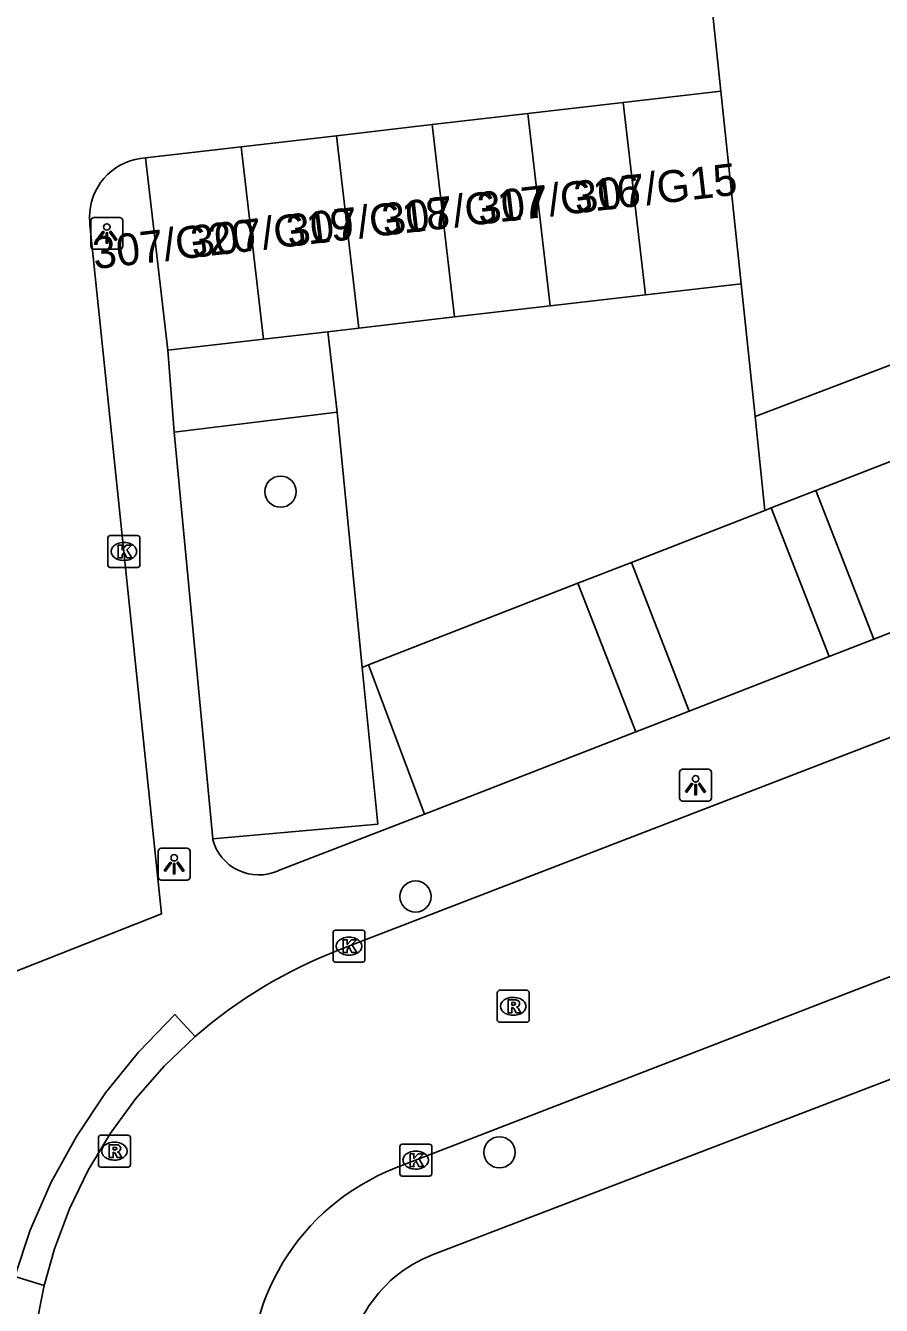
# Model space of a CAD drawing. Extents: x 161253 to 161848, y 384872 to 385383.
# Drawn here: x 161319.1 to 161345.9, y 385275.83 to 385315.91 of the extents above; entities that cross this region are included whole.
import ezdxf

# ---------------------------------------------------------------- set-up
doc = ezdxf.new("R2010")
doc.units = 0
for name, color, linetype in [('IMGEO_Boom', 7, 'Continuous'), ('IMGEO_Groenvoorziening', 7, 'Continuous'), ('IMGEO_Kolk', 7, 'Continuous'), ('IMGEO_Lichtpunt', 7, 'Continuous'), ('IMGEO_Pand', 7, 'Continuous'), ('IMGEO_Pand_nummerreeks', 7, 'Continuous'), ('IMGEO_Parkeervlak_open', 7, 'Continuous'), ('IMGEO_Rijbaan_lokaal_open', 7, 'Continuous'), ('IMGEO_Rioolput', 7, 'Continuous'), ('IMGEO_Voetpad_open', 7, 'Continuous')]:
    doc.layers.add(name, color=color, linetype=linetype)

msp = doc.modelspace()

# ---------------------------------------------------------------- linework, layer by layer
at = {"layer": 'IMGEO_Boom'}
for centre in [(161327.085, 385301.316), (161331.313, 385288.635), (161333.94, 385280.622)]:
    msp.add_circle(centre, 0.489, dxfattribs=at)
at = {"layer": 'IMGEO_Groenvoorziening'}
msp.add_lwpolyline([(161342.253, 385300.73), (161341.943, 385303.675)], dxfattribs=at)
at = {"layer": 'IMGEO_Kolk'}
for p, q in [((161321.677, 385299.017), (161321.677, 385299.869)), ((161321.752, 385299.943), (161322.604, 385299.943)), ((161322.678, 385299.869), (161322.678, 385299.017)), ((161322.165, 385299.723), (161322.19, 385299.723)), ((161322.188, 385299.163), (161322.163, 385299.163)), ((161322.604, 385298.943), (161321.752, 385298.943)), ((161328.727, 385286.654), (161328.727, 385287.506)), ((161328.802, 385287.58), (161329.654, 385287.58)), ((161329.215, 385287.36), (161329.24, 385287.36)), ((161329.728, 385287.506), (161329.728, 385286.654)), ((161329.654, 385286.58), (161328.802, 385286.58)), ((161329.238, 385286.8), (161329.213, 385286.8)), ((161330.818, 385279.952), (161330.818, 385280.804)), ((161330.893, 385280.878), (161331.745, 385280.878)), ((161331.306, 385280.658), (161331.331, 385280.658)), ((161331.819, 385280.804), (161331.819, 385279.952)), ((161331.745, 385279.878), (161330.893, 385279.878)), ((161331.329, 385280.098), (161331.304, 385280.098))]:
    msp.add_line(p, q, dxfattribs=at)
for points in [[(161321.677, 385299.017), (161321.677, 385299.869)], [(161321.752, 385299.943), (161322.604, 385299.943)], [(161322.678, 385299.869), (161322.678, 385299.017)], [(161321.998, 385299.643), (161322.121, 385299.643), (161322.121, 385299.492), (161322.251, 385299.643), (161322.415, 385299.643), (161322.269, 385299.492), (161322.422, 385299.243), (161322.27, 385299.243), (161322.185, 385299.407), (161322.121, 385299.34), (161322.121, 385299.243), (161321.998, 385299.243), (161321.998, 385299.643)], [(161322.604, 385298.943), (161321.752, 385298.943)], [(161328.727, 385286.654), (161328.727, 385287.506)], [(161328.802, 385287.58), (161329.654, 385287.58)], [(161329.728, 385287.506), (161329.728, 385286.654)], [(161329.048, 385287.28), (161329.171, 385287.28), (161329.171, 385287.129), (161329.301, 385287.28), (161329.465, 385287.28), (161329.319, 385287.129), (161329.472, 385286.88), (161329.32, 385286.88), (161329.235, 385287.044), (161329.171, 385286.977), (161329.171, 385286.88), (161329.048, 385286.88), (161329.048, 385287.28)], [(161329.654, 385286.58), (161328.802, 385286.58)], [(161330.818, 385279.952), (161330.818, 385280.804)], [(161330.893, 385280.878), (161331.745, 385280.878)], [(161331.139, 385280.578), (161331.262, 385280.578), (161331.262, 385280.427), (161331.392, 385280.578), (161331.556, 385280.578), (161331.41, 385280.427), (161331.563, 385280.178), (161331.411, 385280.178), (161331.326, 385280.342), (161331.262, 385280.275), (161331.262, 385280.178), (161331.139, 385280.178), (161331.139, 385280.578)], [(161331.819, 385280.804), (161331.819, 385279.952)], [(161331.745, 385279.878), (161330.893, 385279.878)]]:
    msp.add_lwpolyline(points, dxfattribs=at)
for centre, start, end in [((161321.754, 385299.867), 91.552, 178.448), ((161321.754, 385299.867), 91.552, 178.448), ((161322.602, 385299.867), 1.552, 88.448), ((161322.602, 385299.867), 1.552, 88.448), ((161321.754, 385299.019), 181.552, 268.448), ((161321.754, 385299.019), 181.552, 268.448), ((161322.602, 385299.019), 271.552, 358.448), ((161322.602, 385299.019), 271.552, 358.448), ((161328.804, 385287.504), 91.552, 178.448), ((161328.804, 385287.504), 91.552, 178.448), ((161329.652, 385287.504), 1.552, 88.448), ((161329.652, 385287.504), 1.552, 88.448), ((161328.804, 385286.656), 181.552, 268.448), ((161328.804, 385286.656), 181.552, 268.448), ((161329.652, 385286.656), 271.552, 358.448), ((161329.652, 385286.656), 271.552, 358.448), ((161330.895, 385280.802), 91.552, 178.448), ((161330.895, 385280.802), 91.552, 178.448), ((161331.743, 385280.802), 1.552, 88.448), ((161331.743, 385280.802), 1.552, 88.448), ((161330.895, 385279.954), 181.552, 268.448), ((161330.895, 385279.954), 181.552, 268.448), ((161331.743, 385279.954), 271.552, 358.448), ((161331.743, 385279.954), 271.552, 358.448)]:
    msp.add_arc(centre, 0.0765, start, end, dxfattribs=at)
for centre, major_axis, ratio, start_param, end_param in [((161322.164, 385299.443), (-0.387, 0.002), 0.722429, 4.712389, 7.853982), ((161322.189, 385299.443), (-0.39, 0.002), 0.717154, 1.570796, 4.712389), ((161329.214, 385287.08), (-0.387, 0.002), 0.722429, 4.712389, 7.853982), ((161329.239, 385287.08), (-0.39, 0.002), 0.717154, 1.570796, 4.712389), ((161331.305, 385280.378), (-0.387, 0.002), 0.722429, 4.712389, 7.853982), ((161331.33, 385280.378), (-0.39, 0.002), 0.717154, 1.570796, 4.712389)]:
    msp.add_ellipse(centre, major_axis=major_axis, ratio=ratio, start_param=start_param, end_param=end_param, dxfattribs=at)
at = {"layer": 'IMGEO_Lichtpunt'}
for p, q in [((161321.144, 385309.808), (161321.144, 385309.001)), ((161321.144, 385309.808), (161321.144, 385309.001)), ((161322.046, 385309.903), (161321.238, 385309.903)), ((161322.046, 385309.903), (161321.238, 385309.903)), ((161322.14, 385309.001), (161322.14, 385309.808)), ((161322.14, 385309.001), (161322.14, 385309.808)), ((161321.238, 385308.907), (161322.046, 385308.907)), ((161321.238, 385308.907), (161322.046, 385308.907)), ((161340.485, 385292.62), (161339.677, 385292.62)), ((161340.485, 385292.62), (161339.677, 385292.62)), ((161339.583, 385292.525), (161339.583, 385291.718)), ((161339.583, 385292.525), (161339.583, 385291.718)), ((161340.579, 385291.718), (161340.579, 385292.525)), ((161340.579, 385291.718), (161340.579, 385292.525)), ((161339.677, 385291.624), (161340.485, 385291.624)), ((161339.677, 385291.624), (161340.485, 385291.624)), ((161323.254, 385290.051), (161323.254, 385289.244)), ((161323.254, 385290.051), (161323.254, 385289.244)), ((161324.156, 385290.146), (161323.348, 385290.146)), ((161324.156, 385290.146), (161323.348, 385290.146)), ((161324.25, 385289.244), (161324.25, 385290.051)), ((161324.25, 385289.244), (161324.25, 385290.051)), ((161323.348, 385289.15), (161324.156, 385289.15)), ((161323.348, 385289.15), (161324.156, 385289.15))]:
    msp.add_line(p, q, dxfattribs=at)
for points in [[(161321.518, 385309.472), (161321.557, 385309.444), (161321.369, 385309.182), (161321.331, 385309.209), (161321.518, 385309.472)], [(161321.62, 385309.424), (161321.667, 385309.424), (161321.667, 385309.102), (161321.62, 385309.102), (161321.62, 385309.424)], [(161321.73, 385309.444), (161321.768, 385309.471), (161321.955, 385309.209), (161321.916, 385309.181), (161321.73, 385309.444)], [(161339.957, 385292.189), (161339.996, 385292.161), (161339.808, 385291.899), (161339.77, 385291.926), (161339.957, 385292.189)], [(161340.169, 385292.161), (161340.207, 385292.188), (161340.394, 385291.926), (161340.355, 385291.898), (161340.169, 385292.161)], [(161340.059, 385292.141), (161340.106, 385292.141), (161340.106, 385291.819), (161340.059, 385291.819), (161340.059, 385292.141)], [(161323.628, 385289.715), (161323.667, 385289.687), (161323.479, 385289.425), (161323.441, 385289.452), (161323.628, 385289.715)], [(161323.73, 385289.667), (161323.777, 385289.667), (161323.777, 385289.345), (161323.73, 385289.345), (161323.73, 385289.667)], [(161323.84, 385289.687), (161323.878, 385289.714), (161324.065, 385289.452), (161324.026, 385289.424), (161323.84, 385289.687)]]:
    msp.add_lwpolyline(points, dxfattribs=at)
for centre in [(161321.643, 385309.606), (161340.082, 385292.323), (161323.753, 385289.849)]:
    msp.add_circle(centre, 0.0994, dxfattribs=at)
for centre, start, end in [((161321.238, 385309.808), 90, 180), ((161321.238, 385309.808), 90, 180), ((161322.046, 385309.808), 0, 90), ((161322.046, 385309.808), 0, 90), ((161321.238, 385309.001), 180, 270), ((161321.238, 385309.001), 180, 270), ((161322.046, 385309.001), 270, 0), ((161322.046, 385309.001), 270, 360), ((161339.677, 385292.525), 90, 180), ((161339.677, 385292.525), 90, 180), ((161340.485, 385292.525), 0, 90), ((161340.485, 385292.525), 0, 90), ((161339.677, 385291.718), 180, 270), ((161339.677, 385291.718), 180, 270), ((161340.485, 385291.718), 270, 0), ((161340.485, 385291.718), 270, 360), ((161323.348, 385290.051), 90, 180), ((161323.348, 385290.051), 90, 180), ((161324.156, 385290.051), 0, 90), ((161324.156, 385290.051), 0, 90), ((161323.348, 385289.244), 180, 270), ((161323.348, 385289.244), 180, 270), ((161324.156, 385289.244), 270, 0), ((161324.156, 385289.244), 270, 360)]:
    msp.add_arc(centre, 0.0946, start, end, dxfattribs=at)
at = {"layer": 'IMGEO_Pand'}
for points in [[(161340.871, 385313.86), (161339.824, 385323.814)], [(161340.871, 385313.86), (161337.816, 385313.505)], [(161341.506, 385307.829), (161340.871, 385313.86)], [(161334.824, 385313.158), (161337.816, 385313.505)], [(161337.816, 385313.505), (161338.515, 385307.482)], [(161331.833, 385312.811), (161334.824, 385313.158)], [(161334.824, 385313.158), (161335.523, 385307.135)], [(161328.841, 385312.464), (161331.833, 385312.811)], [(161331.833, 385312.811), (161332.532, 385306.788)], [(161325.85, 385312.117), (161328.841, 385312.464)], [(161328.841, 385312.464), (161329.54, 385306.441)], [(161325.85, 385312.117), (161322.859, 385311.77)], [(161326.548, 385306.094), (161325.85, 385312.117)], [(161322.859, 385311.77), (161323.557, 385305.747)], [(161359.136, 385309.338), (161359.113, 385309.131), (161357.21, 385308.445), (161357.263, 385308.334), (161353.721, 385306.981), (161353.329, 385308.005), (161341.943, 385303.675)], [(161338.515, 385307.482), (161341.506, 385307.829)], [(161341.943, 385303.675), (161341.506, 385307.829)], [(161338.515, 385307.482), (161335.523, 385307.135)], [(161335.523, 385307.135), (161332.532, 385306.788)], [(161332.532, 385306.788), (161329.54, 385306.441)], [(161328.561, 385306.327), (161326.548, 385306.094)], [(161329.54, 385306.441), (161328.561, 385306.327)], [(161323.557, 385305.747), (161326.548, 385306.094)]]:
    msp.add_lwpolyline(points, dxfattribs=at)
at = {"layer": 'IMGEO_Parkeervlak_open'}
for points in [[(161343.848, 385301.35), (161352.373, 385304.672)], [(161328.853, 385303.808), (161329.644, 385295.807)], [(161342.253, 385300.73), (161338.07, 385299.1)], [(161342.45, 385300.807), (161342.253, 385300.73)], [(161336.393, 385298.447), (161329.842, 385295.895)]]:
    msp.add_lwpolyline(points, dxfattribs=at)
at = {"layer": 'IMGEO_Rijbaan_lokaal_open'}
for points in [[(161322.859, 385311.77), (161322.693, 385311.754), (161322.53, 385311.722), (161322.37, 385311.677), (161322.215, 385311.617), (161322.065, 385311.543), (161321.923, 385311.457), (161321.789, 385311.358), (161321.665, 385311.248), (161321.551, 385311.127), (161321.448, 385310.996), (161321.357, 385310.856), (161321.279, 385310.709), (161321.215, 385310.556), (161321.164, 385310.397), (161321.128, 385310.235), (161321.106, 385310.07), (161321.1, 385309.904), (161321.108, 385309.737), (161321.115, 385309.674), (161323.36, 385288.088), (161317.793, 385285.896)], [(161328.923, 385286.962), (161374.2, 385304.421), (161379.805, 385306.58), (161385.091, 385308.618)], [(161356.419, 385290.084), (161330.668, 385280.124)], [(161319.678, 385276.452), (161319.999, 385277.598), (161320.475, 385278.856), (161321.063, 385280.067), (161321.756, 385281.221), (161322.549, 385282.308), (161323.437, 385283.32), (161324.411, 385284.249)], [(161327.141, 385199.049), (161326.822, 385201.971), (161321.575, 385250), (161319.33, 385271.321), (161319.259, 385272.292), (161319.265, 385273.638), (161319.391, 385274.978), (161319.678, 385276.452)]]:
    msp.add_lwpolyline(points, dxfattribs=at)
for centre, radius, start, end in [((161334.322, 385272.875), 15.087, 110.9691, 131.0667), ((161333.288, 385273.455), 7.166, 111.4479, 186.0931)]:
    msp.add_arc(centre, radius, start, end, dxfattribs=at)
at = {"layer": 'IMGEO_Rioolput'}
for p, q in [((161333.871, 385284.771), (161333.871, 385285.623)), ((161333.946, 385285.697), (161334.798, 385285.697)), ((161334.359, 385285.477), (161334.384, 385285.477)), ((161334.872, 385285.623), (161334.872, 385284.771)), ((161334.798, 385284.697), (161333.946, 385284.697)), ((161334.382, 385284.917), (161334.357, 385284.917)), ((161321.38, 385280.234), (161321.38, 385281.086)), ((161321.455, 385281.16), (161322.307, 385281.16)), ((161321.868, 385280.94), (161321.893, 385280.94)), ((161322.381, 385281.086), (161322.381, 385280.234)), ((161322.307, 385280.16), (161321.455, 385280.16)), ((161321.891, 385280.38), (161321.866, 385280.38))]:
    msp.add_line(p, q, dxfattribs=at)
for points in [[(161333.871, 385284.771), (161333.871, 385285.623)], [(161333.946, 385285.697), (161334.798, 385285.697)], [(161334.46, 385285.395), (161334.208, 385285.397), (161334.208, 385284.997)], [(161334.872, 385285.623), (161334.872, 385284.771)], [(161334.208, 385284.997), (161334.332, 385284.997), (161334.332, 385285.159), (161334.343, 385285.159)], [(161334.386, 385285.316), (161334.332, 385285.316), (161334.332, 385285.235)], [(161334.332, 385285.235), (161334.384, 385285.235)], [(161334.39, 385285.13), (161334.461, 385284.997), (161334.601, 385284.997), (161334.536, 385285.123)], [(161334.798, 385284.697), (161333.946, 385284.697)], [(161321.38, 385280.234), (161321.38, 385281.086)], [(161321.455, 385281.16), (161322.307, 385281.16)], [(161322.381, 385281.086), (161322.381, 385280.234)], [(161321.969, 385280.858), (161321.717, 385280.86), (161321.717, 385280.46)], [(161321.717, 385280.46), (161321.841, 385280.46), (161321.841, 385280.622), (161321.852, 385280.622)], [(161321.895, 385280.779), (161321.841, 385280.779), (161321.841, 385280.698)], [(161321.841, 385280.698), (161321.893, 385280.698)], [(161321.899, 385280.593), (161321.97, 385280.46), (161322.11, 385280.46), (161322.045, 385280.586)], [(161322.307, 385280.16), (161321.455, 385280.16)]]:
    msp.add_lwpolyline(points, dxfattribs=at)
for centre, radius, start, end in [((161333.948, 385285.621), 0.0765, 91.552, 178.448), ((161333.948, 385285.621), 0.0765, 91.552, 178.448), ((161334.459, 385285.285), 0.109, 350.3612, 89.416), ((161334.796, 385285.621), 0.0765, 1.552, 88.448), ((161334.796, 385285.621), 0.0765, 1.552, 88.448), ((161334.342, 385285.106), 0.0533, 26.0293, 88.6989), ((161334.368, 385285.424), 0.19, 274.7715, 282.9687), ((161334.392, 385285.22), 0.0964, 77.0061, 93.1865), ((161334.406, 385285.277), 0.0378, 276.6634, 79.6772), ((161334.457, 385285.285), 0.112, 277.5842, 350.9817), ((161334.441, 385285.07), 0.108, 29.5134, 73.7905), ((161333.948, 385284.773), 0.0765, 181.552, 268.448), ((161333.948, 385284.773), 0.0765, 181.552, 268.448), ((161334.796, 385284.773), 0.0765, 271.552, 358.448), ((161334.796, 385284.773), 0.0765, 271.552, 358.448), ((161321.457, 385281.084), 0.0765, 91.552, 178.448), ((161321.457, 385281.084), 0.0765, 91.552, 178.448), ((161322.305, 385281.084), 0.0765, 1.552, 88.448), ((161322.305, 385281.084), 0.0765, 1.552, 88.448), ((161321.851, 385280.569), 0.0533, 26.0293, 88.6989), ((161321.877, 385280.887), 0.19, 274.7715, 282.9687), ((161321.901, 385280.683), 0.0964, 77.0061, 93.1865), ((161321.915, 385280.74), 0.0378, 276.6634, 79.6772), ((161321.968, 385280.748), 0.109, 350.3612, 89.416), ((161321.966, 385280.748), 0.112, 277.5842, 350.9817), ((161321.95, 385280.533), 0.108, 29.5134, 73.7905), ((161321.457, 385280.236), 0.0765, 181.552, 268.448), ((161321.457, 385280.236), 0.0765, 181.552, 268.448), ((161322.305, 385280.236), 0.0765, 271.552, 358.448), ((161322.305, 385280.236), 0.0765, 271.552, 358.448)]:
    msp.add_arc(centre, radius, start, end, dxfattribs=at)
for centre, major_axis, ratio, start_param, end_param in [((161334.358, 385285.197), (-0.387, 0.002), 0.722429, 4.712389, 7.853982), ((161334.383, 385285.197), (-0.39, 0.002), 0.717154, 1.570796, 4.712389), ((161321.867, 385280.66), (-0.387, 0.002), 0.722429, 4.712389, 7.853982), ((161321.892, 385280.66), (-0.39, 0.002), 0.717154, 1.570796, 4.712389)]:
    msp.add_ellipse(centre, major_axis=major_axis, ratio=ratio, start_param=start_param, end_param=end_param, dxfattribs=at)
at = {"layer": 'IMGEO_Voetpad_open'}
for points in [[(161328.561, 385306.327), (161328.853, 385303.808)], [(161323.752, 385303.182), (161323.557, 385305.747)], [(161323.752, 385303.182), (161328.853, 385303.808)], [(161324.958, 385290.439), (161323.752, 385303.182)], [(161343.848, 385301.35), (161342.45, 385300.807)], [(161345.661, 385296.695), (161343.848, 385301.35)], [(161342.45, 385300.807), (161344.263, 385296.151)], [(161354.187, 385300.016), (161345.661, 385296.695)], [(161336.393, 385298.447), (161338.07, 385299.1)], [(161338.07, 385299.1), (161339.883, 385294.445)], [(161338.206, 385293.792), (161336.393, 385298.447)], [(161344.263, 385296.151), (161345.661, 385296.695)], [(161329.644, 385295.807), (161330.129, 385290.905), (161324.958, 385290.439)], [(161329.644, 385295.807), (161329.842, 385295.895)], [(161329.842, 385295.895), (161331.59, 385291.215)], [(161339.883, 385294.445), (161344.263, 385296.151)], [(161338.206, 385293.792), (161339.883, 385294.445)], [(161331.59, 385291.215), (161338.206, 385293.792)], [(161327.022, 385289.445), (161331.59, 385291.215)], [(161354.019, 385285.915), (161331.859, 385277.42)], [(161324.411, 385284.249), (161323.77, 385284.937), (161322.63, 385283.759), (161321.6, 385282.484), (161320.689, 385281.122), (161319.902, 385279.684), (161319.247, 385278.182), (161318.759, 385276.732), (161319.678, 385276.452)]]:
    msp.add_lwpolyline(points, dxfattribs=at)
for centre, radius, start, end in [((161326.403, 385290.8), 1.49, 194.0358, 294.5343), ((161333.382, 385273.465), 4.239, 111.0615, 186.2663)]:
    msp.add_arc(centre, radius, start, end, dxfattribs=at)

# ---------------------------------------------------------------- texts
at = {"layer": 'IMGEO_Pand_nummerreeks'}
for s, p in [('307/G15', (161336.333, 385310.031)), ('307/G16', (161333.31, 385309.681)), ('307/G17', (161330.318, 385309.334)), ('307/G19', (161324.332, 385308.639)), ('307/G18', (161327.33, 385308.987)), ('307/G20', (161321.257, 385308.282))]:
    msp.add_text(s, height=1, rotation=6.6186, dxfattribs=at).set_placement(p)

doc.saveas('drawing.dxf')
